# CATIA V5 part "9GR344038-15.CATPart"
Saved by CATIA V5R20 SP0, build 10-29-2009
Part number: 9GR344038-15
Revision: ANY
Definition: UNKNOWN
Nomenclature: 9GR344038-15
Source: Unknown
Bounding box of the stored display mesh (mm): x -18.905 to 18.807, y -35 to 5, z -19 to 19
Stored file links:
  C:\Users\Utente\Desktop\IO LAVORO\3D X SITO CF\CUMSA\3D files GR\GR 344038-15\9GR344038-15.CATPart
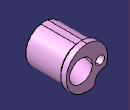
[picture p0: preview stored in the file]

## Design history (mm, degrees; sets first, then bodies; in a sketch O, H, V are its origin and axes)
Body1 "Cortar-Extruir7" (main body)
  Solid1: solid without history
